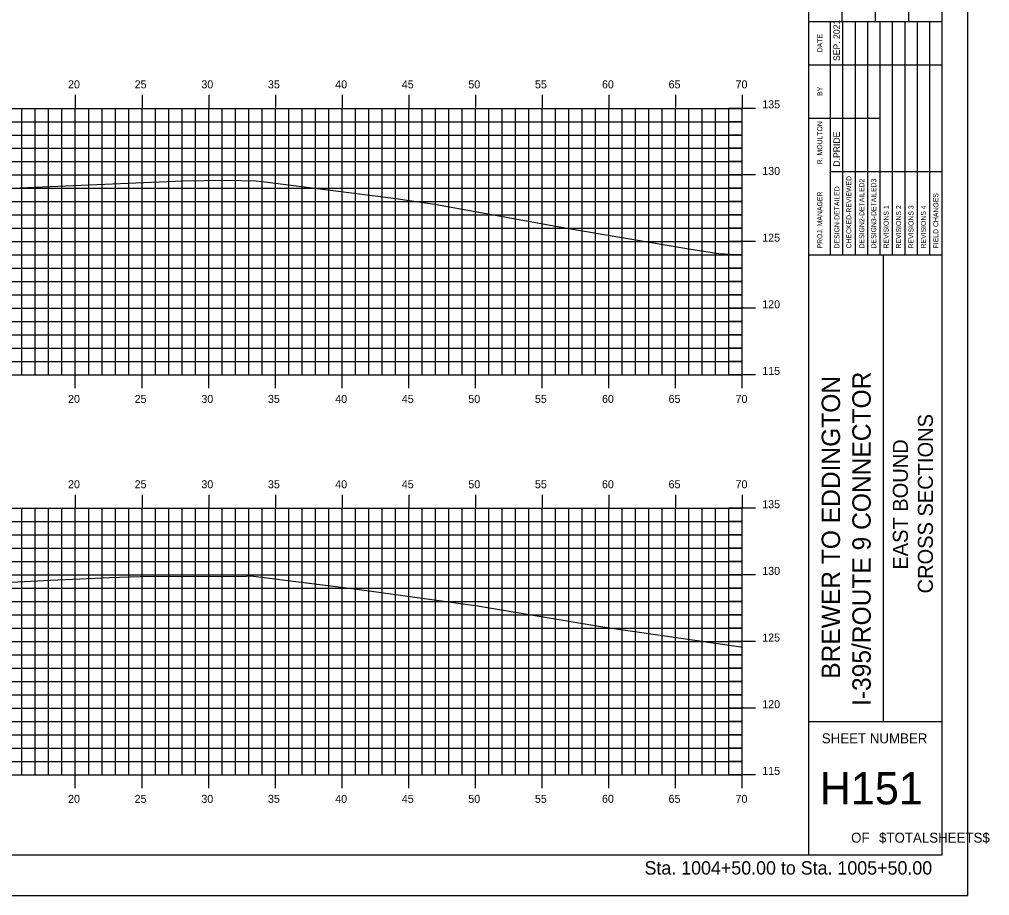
# Model space of a CAD drawing. Extents: x 851295 to 851467, y 365624 to 365734.
# Drawn here: x 851393.8 to 851466.6, y 365624 to 365689.7 of the extents above; entities that cross this region are included whole.
import ezdxf

# ---------------------------------------------------------------- set-up
doc = ezdxf.new("R2010")
doc.units = 0
for name, color, linetype in [('BORDER', 7, 'Continuous'), ('H_V ANNOTATION', 7, 'Continuous'), ('MAJOR', 7, 'Continuous'), ('MINOR', 7, 'Continuous'), ('PLOT BOUNDARY', 7, 'Continuous'), ('S_Roadway_Centerline', 7, 'Continuous')]:
    doc.layers.add(name, color=color, linetype=linetype)

msp = doc.modelspace()

# ---------------------------------------------------------------- linework, layer by layer
at = {"layer": 'BORDER'}
for p, q in [((851453.009, 365627.027), (851453.009, 365732.027)), ((851455.509, 365689.53), (851455.509, 365698.177)), ((851458.009, 365689.53), (851458.009, 365698.177)), ((851460.509, 365689.53), (851460.509, 365698.177)), ((851453.009, 365689.53), (851463.009, 365689.53)), ((851453.009, 365672.03), (851463.009, 365672.03)), ((851458.6, 365637.03), (851458.6, 365672.03)), ((851453.009, 365637.03), (851463.009, 365637.03))]:
    msp.add_line(p, q, dxfattribs=at)
msp.add_lwpolyline([(851303.009, 365627.027), (851463.009, 365627.027), (851463.009, 365732.027), (851303.009, 365732.027)], close=True, dxfattribs=at)
for points in [[(851454.624, 365686.28), (851454.624, 365689.53)], [(851455.557, 365672.033), (851455.557, 365689.53)], [(851456.488, 365689.53), (851456.488, 365672.033)], [(851457.42, 365672.033), (851457.42, 365689.53)], [(851458.352, 365672.033), (851458.352, 365689.53)], [(851459.283, 365672.033), (851459.283, 365689.53)], [(851460.215, 365672.033), (851460.215, 365689.53)], [(851461.147, 365672.033), (851461.147, 365689.53)], [(851462.079, 365672.033), (851462.079, 365689.53)], [(851454.625, 365672.033), (851454.625, 365688.824)], [(851453.009, 365686.28), (851463.009, 365686.28)], [(851453.009, 365682.28), (851454.625, 365682.28)], [(851454.624, 365682.28), (851458.351, 365682.28)], [(851454.624, 365678.28), (851463.009, 365678.28)]]:
    msp.add_lwpolyline(points, dxfattribs=at)
at = {"layer": 'MAJOR'}
for p, q in [((851398.009, 365684.029), (851398.009, 365683.027)), ((851403.009, 365684.029), (851403.009, 365683.027)), ((851408.009, 365684.029), (851408.009, 365683.027)), ((851413.009, 365684.029), (851413.009, 365683.027)), ((851418.009, 365684.029), (851418.009, 365683.027)), ((851423.009, 365684.029), (851423.009, 365683.027)), ((851428.009, 365684.029), (851428.009, 365683.027)), ((851433.009, 365684.029), (851433.009, 365683.027)), ((851438.009, 365684.029), (851438.009, 365683.027)), ((851443.009, 365684.029), (851443.009, 365683.027)), ((851448.009, 365684.029), (851448.009, 365683.027)), ((851308.009, 365683.027), (851448.009, 365683.027)), ((851308.009, 365683.027), (851448.009, 365683.027)), ((851398.009, 365663.027), (851398.009, 365683.027)), ((851403.009, 365663.027), (851403.009, 365683.027)), ((851408.009, 365663.027), (851408.009, 365683.027)), ((851413.009, 365663.027), (851413.009, 365683.027)), ((851418.009, 365663.027), (851418.009, 365683.027)), ((851423.009, 365663.027), (851423.009, 365683.027)), ((851428.009, 365663.027), (851428.009, 365683.027)), ((851433.009, 365663.027), (851433.009, 365683.027)), ((851438.009, 365663.027), (851438.009, 365683.027)), ((851443.009, 365663.027), (851443.009, 365683.027)), ((851449.011, 365683.027), (851447.007, 365683.027)), ((851448.009, 365663.027), (851448.009, 365683.027)), ((851448.009, 365663.027), (851448.009, 365683.027)), ((851308.009, 365678.027), (851448.009, 365678.027)), ((851449.011, 365678.027), (851447.007, 365678.027)), ((851308.009, 365673.027), (851448.009, 365673.027)), ((851449.011, 365673.027), (851447.007, 365673.027)), ((851308.009, 365668.027), (851448.009, 365668.027)), ((851449.011, 365668.027), (851447.007, 365668.027)), ((851308.009, 365663.027), (851448.009, 365663.027)), ((851308.009, 365663.027), (851448.009, 365663.027)), ((851398.009, 365662.025), (851398.009, 365663.027)), ((851403.009, 365662.025), (851403.009, 365663.027)), ((851408.009, 365662.025), (851408.009, 365663.027)), ((851413.009, 365662.025), (851413.009, 365663.027)), ((851418.009, 365662.025), (851418.009, 365663.027)), ((851423.009, 365662.025), (851423.009, 365663.027)), ((851428.009, 365662.025), (851428.009, 365663.027)), ((851433.009, 365662.025), (851433.009, 365663.027)), ((851438.009, 365662.025), (851438.009, 365663.027)), ((851443.009, 365662.025), (851443.009, 365663.027)), ((851449.011, 365663.027), (851447.007, 365663.027)), ((851448.009, 365662.025), (851448.009, 365663.027)), ((851398.009, 365654.029), (851398.009, 365653.027)), ((851403.009, 365654.029), (851403.009, 365653.027)), ((851408.009, 365654.029), (851408.009, 365653.027)), ((851413.009, 365654.029), (851413.009, 365653.027)), ((851418.009, 365654.029), (851418.009, 365653.027)), ((851423.009, 365654.029), (851423.009, 365653.027)), ((851428.009, 365654.029), (851428.009, 365653.027)), ((851433.009, 365654.029), (851433.009, 365653.027)), ((851438.009, 365654.029), (851438.009, 365653.027)), ((851443.009, 365654.029), (851443.009, 365653.027)), ((851448.009, 365654.029), (851448.009, 365653.027)), ((851308.009, 365653.027), (851448.009, 365653.027)), ((851308.009, 365653.027), (851448.009, 365653.027)), ((851398.009, 365633.027), (851398.009, 365653.027)), ((851403.009, 365633.027), (851403.009, 365653.027)), ((851408.009, 365633.027), (851408.009, 365653.027)), ((851413.009, 365633.027), (851413.009, 365653.027)), ((851418.009, 365633.027), (851418.009, 365653.027)), ((851423.009, 365633.027), (851423.009, 365653.027)), ((851428.009, 365633.027), (851428.009, 365653.027)), ((851433.009, 365633.027), (851433.009, 365653.027)), ((851438.009, 365633.027), (851438.009, 365653.027)), ((851443.009, 365633.027), (851443.009, 365653.027)), ((851449.011, 365653.027), (851447.007, 365653.027)), ((851448.009, 365633.027), (851448.009, 365653.027)), ((851448.009, 365633.027), (851448.009, 365653.027)), ((851308.009, 365648.027), (851448.009, 365648.027)), ((851449.011, 365648.027), (851447.007, 365648.027)), ((851308.009, 365643.027), (851448.009, 365643.027)), ((851449.011, 365643.027), (851447.007, 365643.027)), ((851308.009, 365638.027), (851448.009, 365638.027)), ((851449.011, 365638.027), (851447.007, 365638.027)), ((851308.009, 365633.027), (851448.009, 365633.027)), ((851308.009, 365633.027), (851448.009, 365633.027)), ((851398.009, 365632.025), (851398.009, 365633.027)), ((851403.009, 365632.025), (851403.009, 365633.027)), ((851408.009, 365632.025), (851408.009, 365633.027)), ((851413.009, 365632.025), (851413.009, 365633.027)), ((851418.009, 365632.025), (851418.009, 365633.027)), ((851423.009, 365632.025), (851423.009, 365633.027)), ((851428.009, 365632.025), (851428.009, 365633.027)), ((851433.009, 365632.025), (851433.009, 365633.027)), ((851438.009, 365632.025), (851438.009, 365633.027)), ((851443.009, 365632.025), (851443.009, 365633.027)), ((851449.011, 365633.027), (851447.007, 365633.027)), ((851448.009, 365632.025), (851448.009, 365633.027))]:
    msp.add_line(p, q, dxfattribs=at)
at = {"layer": 'MINOR'}
for p, q in [((851394.009, 365663.027), (851394.009, 365683.027)), ((851395.009, 365663.027), (851395.009, 365683.027)), ((851396.009, 365663.027), (851396.009, 365683.027)), ((851397.009, 365663.027), (851397.009, 365683.027)), ((851399.009, 365663.027), (851399.009, 365683.027)), ((851400.009, 365663.027), (851400.009, 365683.027)), ((851401.009, 365663.027), (851401.009, 365683.027)), ((851402.009, 365663.027), (851402.009, 365683.027)), ((851404.009, 365663.027), (851404.009, 365683.027)), ((851405.009, 365663.027), (851405.009, 365683.027)), ((851406.009, 365663.027), (851406.009, 365683.027)), ((851407.009, 365663.027), (851407.009, 365683.027)), ((851409.009, 365663.027), (851409.009, 365683.027)), ((851410.009, 365663.027), (851410.009, 365683.027)), ((851411.009, 365663.027), (851411.009, 365683.027)), ((851412.009, 365663.027), (851412.009, 365683.027)), ((851414.009, 365663.027), (851414.009, 365683.027)), ((851415.009, 365663.027), (851415.009, 365683.027)), ((851416.009, 365663.027), (851416.009, 365683.027)), ((851417.009, 365663.027), (851417.009, 365683.027)), ((851419.009, 365663.027), (851419.009, 365683.027)), ((851420.009, 365663.027), (851420.009, 365683.027)), ((851421.009, 365663.027), (851421.009, 365683.027)), ((851422.009, 365663.027), (851422.009, 365683.027)), ((851424.009, 365663.027), (851424.009, 365683.027)), ((851425.009, 365663.027), (851425.009, 365683.027)), ((851426.009, 365663.027), (851426.009, 365683.027)), ((851427.009, 365663.027), (851427.009, 365683.027)), ((851429.009, 365663.027), (851429.009, 365683.027)), ((851430.009, 365663.027), (851430.009, 365683.027)), ((851431.009, 365663.027), (851431.009, 365683.027)), ((851432.009, 365663.027), (851432.009, 365683.027)), ((851434.009, 365663.027), (851434.009, 365683.027)), ((851435.009, 365663.027), (851435.009, 365683.027)), ((851436.009, 365663.027), (851436.009, 365683.027)), ((851437.009, 365663.027), (851437.009, 365683.027)), ((851439.009, 365663.027), (851439.009, 365683.027)), ((851440.009, 365663.027), (851440.009, 365683.027)), ((851441.009, 365663.027), (851441.009, 365683.027)), ((851442.009, 365663.027), (851442.009, 365683.027)), ((851444.009, 365663.027), (851444.009, 365683.027)), ((851445.009, 365663.027), (851445.009, 365683.027)), ((851446.009, 365663.027), (851446.009, 365683.027)), ((851447.009, 365663.027), (851447.009, 365683.027)), ((851308.009, 365682.027), (851448.009, 365682.027)), ((851448.009, 365682.027), (851447.007, 365682.027)), ((851308.009, 365681.027), (851448.009, 365681.027)), ((851448.009, 365681.027), (851447.007, 365681.027)), ((851308.009, 365680.027), (851448.009, 365680.027)), ((851448.009, 365680.027), (851447.007, 365680.027)), ((851308.009, 365679.027), (851448.009, 365679.027)), ((851448.009, 365679.027), (851447.007, 365679.027)), ((851308.009, 365677.027), (851448.009, 365677.027)), ((851448.009, 365677.027), (851447.007, 365677.027)), ((851308.009, 365676.027), (851448.009, 365676.027)), ((851448.009, 365676.027), (851447.007, 365676.027)), ((851308.009, 365675.027), (851448.009, 365675.027)), ((851448.009, 365675.027), (851447.007, 365675.027)), ((851308.009, 365674.027), (851448.009, 365674.027)), ((851448.009, 365674.027), (851447.007, 365674.027)), ((851308.009, 365672.027), (851448.009, 365672.027)), ((851448.009, 365672.027), (851447.007, 365672.027)), ((851308.009, 365671.027), (851448.009, 365671.027)), ((851448.009, 365671.027), (851447.007, 365671.027)), ((851308.009, 365670.027), (851448.009, 365670.027)), ((851448.009, 365670.027), (851447.007, 365670.027)), ((851308.009, 365669.027), (851448.009, 365669.027)), ((851448.009, 365669.027), (851447.007, 365669.027)), ((851308.009, 365667.027), (851448.009, 365667.027)), ((851448.009, 365667.027), (851447.007, 365667.027)), ((851308.009, 365666.027), (851448.009, 365666.027)), ((851448.009, 365666.027), (851447.007, 365666.027)), ((851308.009, 365665.027), (851448.009, 365665.027)), ((851448.009, 365665.027), (851447.007, 365665.027)), ((851308.009, 365664.027), (851448.009, 365664.027)), ((851448.009, 365664.027), (851447.007, 365664.027)), ((851394.009, 365633.027), (851394.009, 365653.027)), ((851395.009, 365633.027), (851395.009, 365653.027)), ((851396.009, 365633.027), (851396.009, 365653.027)), ((851397.009, 365633.027), (851397.009, 365653.027)), ((851399.009, 365633.027), (851399.009, 365653.027)), ((851400.009, 365633.027), (851400.009, 365653.027)), ((851401.009, 365633.027), (851401.009, 365653.027)), ((851402.009, 365633.027), (851402.009, 365653.027)), ((851404.009, 365633.027), (851404.009, 365653.027)), ((851405.009, 365633.027), (851405.009, 365653.027)), ((851406.009, 365633.027), (851406.009, 365653.027)), ((851407.009, 365633.027), (851407.009, 365653.027)), ((851409.009, 365633.027), (851409.009, 365653.027)), ((851410.009, 365633.027), (851410.009, 365653.027)), ((851411.009, 365633.027), (851411.009, 365653.027)), ((851412.009, 365633.027), (851412.009, 365653.027)), ((851414.009, 365633.027), (851414.009, 365653.027)), ((851415.009, 365633.027), (851415.009, 365653.027)), ((851416.009, 365633.027), (851416.009, 365653.027)), ((851417.009, 365633.027), (851417.009, 365653.027)), ((851419.009, 365633.027), (851419.009, 365653.027)), ((851420.009, 365633.027), (851420.009, 365653.027)), ((851421.009, 365633.027), (851421.009, 365653.027)), ((851422.009, 365633.027), (851422.009, 365653.027)), ((851424.009, 365633.027), (851424.009, 365653.027)), ((851425.009, 365633.027), (851425.009, 365653.027)), ((851426.009, 365633.027), (851426.009, 365653.027)), ((851427.009, 365633.027), (851427.009, 365653.027)), ((851429.009, 365633.027), (851429.009, 365653.027)), ((851430.009, 365633.027), (851430.009, 365653.027)), ((851431.009, 365633.027), (851431.009, 365653.027)), ((851432.009, 365633.027), (851432.009, 365653.027)), ((851434.009, 365633.027), (851434.009, 365653.027)), ((851435.009, 365633.027), (851435.009, 365653.027)), ((851436.009, 365633.027), (851436.009, 365653.027)), ((851437.009, 365633.027), (851437.009, 365653.027)), ((851439.009, 365633.027), (851439.009, 365653.027)), ((851440.009, 365633.027), (851440.009, 365653.027)), ((851441.009, 365633.027), (851441.009, 365653.027)), ((851442.009, 365633.027), (851442.009, 365653.027)), ((851444.009, 365633.027), (851444.009, 365653.027)), ((851445.009, 365633.027), (851445.009, 365653.027)), ((851446.009, 365633.027), (851446.009, 365653.027)), ((851447.009, 365633.027), (851447.009, 365653.027)), ((851308.009, 365652.027), (851448.009, 365652.027)), ((851448.009, 365652.027), (851447.007, 365652.027)), ((851308.009, 365651.027), (851448.009, 365651.027)), ((851448.009, 365651.027), (851447.007, 365651.027)), ((851308.009, 365650.027), (851448.009, 365650.027)), ((851448.009, 365650.027), (851447.007, 365650.027)), ((851308.009, 365649.027), (851448.009, 365649.027)), ((851448.009, 365649.027), (851447.007, 365649.027)), ((851308.009, 365647.027), (851448.009, 365647.027)), ((851448.009, 365647.027), (851447.007, 365647.027)), ((851308.009, 365646.027), (851448.009, 365646.027)), ((851448.009, 365646.027), (851447.007, 365646.027)), ((851308.009, 365645.027), (851448.009, 365645.027)), ((851448.009, 365645.027), (851447.007, 365645.027)), ((851308.009, 365644.027), (851448.009, 365644.027)), ((851448.009, 365644.027), (851447.007, 365644.027)), ((851308.009, 365642.027), (851448.009, 365642.027)), ((851448.009, 365642.027), (851447.007, 365642.027)), ((851308.009, 365641.027), (851448.009, 365641.027)), ((851448.009, 365641.027), (851447.007, 365641.027)), ((851308.009, 365640.027), (851448.009, 365640.027)), ((851448.009, 365640.027), (851447.007, 365640.027)), ((851308.009, 365639.027), (851448.009, 365639.027)), ((851448.009, 365639.027), (851447.007, 365639.027)), ((851308.009, 365637.027), (851448.009, 365637.027)), ((851448.009, 365637.027), (851447.007, 365637.027)), ((851308.009, 365636.027), (851448.009, 365636.027)), ((851448.009, 365636.027), (851447.007, 365636.027)), ((851308.009, 365635.027), (851448.009, 365635.027)), ((851448.009, 365635.027), (851447.007, 365635.027)), ((851308.009, 365634.027), (851448.009, 365634.027)), ((851448.009, 365634.027), (851447.007, 365634.027))]:
    msp.add_line(p, q, dxfattribs=at)
at = {"layer": 'PLOT BOUNDARY'}
msp.add_lwpolyline([(851294.916, 365623.968), (851464.916, 365623.968), (851464.916, 365733.968), (851294.916, 365733.968)], close=True, dxfattribs=at)
at = {"layer": 'S_Roadway_Centerline'}
for points in [[(851392.707, 365677.023), (851396.692, 365677.186), (851406.08, 365677.591), (851409.251, 365677.629), (851411.56, 365677.587), (851412.408, 365677.5), (851421.865, 365676.283), (851424.96, 365675.848), (851434.708, 365674.063), (851443.865, 365672.505), (851446.236, 365672.128), (851448.009, 365672.04)], [(851391.713, 365647.416), (851396.158, 365647.634), (851400.558, 365647.828), (851402.887, 365647.907), (851410.842, 365647.936), (851411.16, 365647.956), (851415.335, 365647.425), (851419.31, 365646.929), (851428.157, 365645.7), (851437.716, 365644.098), (851447.91, 365642.62), (851447.948, 365642.613), (851447.95, 365642.613), (851448.009, 365642.636)]]:
    msp.add_lwpolyline(points, dxfattribs=at)

# ---------------------------------------------------------------- texts
at = {"layer": 'BORDER'}
for s, height, p in [('SEP. 2021', 0.4845, (851455.332, 365686.575)), ('DATE', 0.3714, (851454.014, 365687.235)), ('BY', 0.3714, (851454.014, 365683.965)), ('R. MOULTON', 0.3727, (851454.013, 365678.832)), ('D.PRIDE', 0.4845, (851455.332, 365678.653)), ('CHECKED-REVIEWED', 0.37275, (851456.19, 365672.518)), ('DESIGN2-DETAILED2', 0.37275, (851457.159, 365672.518)), ('DESIGN3-DETAILED3', 0.37275, (851458.054, 365672.518)), ('PROJ. MANAGER', 0.37275, (851454.014, 365672.518)), ('DESIGN-DETAILED', 0.37275, (851455.296, 365672.518)), ('FIELD CHANGES', 0.37275, (851462.712, 365672.518)), ('REVISIONS 1', 0.37275, (851458.985, 365672.518)), ('REVISIONS 2', 0.37275, (851459.917, 365672.518)), ('REVISIONS 3', 0.37275, (851460.849, 365672.518)), ('REVISIONS 4', 0.37275, (851461.78, 365672.518)), ('BREWER TO EDDINGTON', 1.37787, (851455.343, 365640.231)), ('I-395/ROUTE 9 CONNECTOR', 1.37787, (851457.644, 365638.192)), ('CROSS SECTIONS', 1.125, (851462.307, 365646.638)), ('EAST BOUND', 1.125, (851460.428, 365648.418))]:
    msp.add_text(s, height=height, rotation=90, dxfattribs=at).set_placement(p)
for s, height, p in [('SHEET NUMBER', 0.74527, (851453.975, 365635.393)), ('H151', 2.4194, (851453.82, 365630.809)), ('OF', 0.7453, (851456.176, 365627.94)), ('$TOTALSHEETS$', 0.74527, (851458.266, 365627.94))]:
    msp.add_text(s, height=height, dxfattribs=at).set_placement(p)
at = {"layer": 'H_V ANNOTATION'}
for s, height, p in [('20', 0.6, (851397.463, 365684.527)), ('25', 0.6, (851402.455, 365684.527)), ('30', 0.6, (851407.458, 365684.527)), ('35', 0.6, (851412.45, 365684.527)), ('40', 0.6, (851417.495, 365684.527)), ('45', 0.6, (851422.487, 365684.527)), ('50', 0.6, (851427.474, 365684.527)), ('55', 0.6, (851432.466, 365684.527)), ('60', 0.6, (851437.495, 365684.527)), ('65', 0.6, (851442.487, 365684.527)), ('70', 0.6, (851447.511, 365684.527)), ('135', 0.6, (851449.509, 365683.027)), ('130', 0.6, (851449.509, 365678.027)), ('125', 0.6, (851449.509, 365673.027)), ('120', 0.6, (851449.509, 365668.027)), ('115', 0.6, (851449.509, 365663.027)), ('20', 0.6, (851397.463, 365660.927)), ('25', 0.6, (851402.455, 365660.927)), ('30', 0.6, (851407.458, 365660.927)), ('35', 0.6, (851412.45, 365660.927)), ('40', 0.6, (851417.495, 365660.927)), ('45', 0.6, (851422.487, 365660.927)), ('50', 0.6, (851427.474, 365660.927)), ('55', 0.6, (851432.466, 365660.927)), ('60', 0.6, (851437.495, 365660.927)), ('65', 0.6, (851442.487, 365660.927)), ('70', 0.6, (851447.511, 365660.927)), ('20', 0.6, (851397.463, 365654.527)), ('25', 0.6, (851402.455, 365654.527)), ('30', 0.6, (851407.458, 365654.527)), ('35', 0.6, (851412.45, 365654.527)), ('40', 0.6, (851417.495, 365654.527)), ('45', 0.6, (851422.487, 365654.527)), ('50', 0.6, (851427.474, 365654.527)), ('55', 0.6, (851432.466, 365654.527)), ('60', 0.6, (851437.495, 365654.527)), ('65', 0.6, (851442.487, 365654.527)), ('70', 0.6, (851447.511, 365654.527)), ('135', 0.6, (851449.509, 365653.027)), ('130', 0.6, (851449.509, 365648.027)), ('125', 0.6, (851449.509, 365643.027)), ('120', 0.6, (851449.509, 365638.027)), ('115', 0.6, (851449.509, 365633.027)), ('20', 0.6, (851397.463, 365630.927)), ('25', 0.6, (851402.455, 365630.927)), ('30', 0.6, (851407.458, 365630.927)), ('35', 0.6, (851412.45, 365630.927)), ('40', 0.6, (851417.495, 365630.927)), ('45', 0.6, (851422.487, 365630.927)), ('50', 0.6, (851427.474, 365630.927)), ('55', 0.6, (851432.466, 365630.927)), ('60', 0.6, (851437.495, 365630.927)), ('65', 0.6, (851442.487, 365630.927)), ('70', 0.6, (851447.511, 365630.927)), ('Sta. 1004+50.00 to Sta. 1005+50.00', 1.0002, (851440.685, 365625.547))]:
    msp.add_text(s, height=height, dxfattribs=at).set_placement(p)

doc.saveas('drawing.dxf')
